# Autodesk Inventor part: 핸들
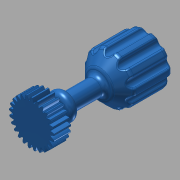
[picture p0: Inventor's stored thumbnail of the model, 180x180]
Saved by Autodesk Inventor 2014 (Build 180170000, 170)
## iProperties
Created: 2017-04
Part Number: 핸들
Material: 강철, 연강
Document SubType Name: Modeling
Designer: mduedu
Categories: <?xml version="1.0" encoding="UTF-16"?> <MemberInstance><Categories><FamilyTemplate><FamilyTemplateParameter ValueType="xs:double" Id="1" ObjectReferenceKey="da
Density: 7.86 g/cm^3
Appearance: 청록색
Mass: 193.539 g
Surface Area: 74.5308 cm^2
Volume: 24.6233 cm^3
CustomPartVersion: 1
Author: mduedu
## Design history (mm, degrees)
sketch "Sketch1"
  geometry: C1 r 13.5 at (0, 0)
  constraints: 1 centre point
  dimensions: "d0" = 27 diameter of C1 (= da_da)
extrude "Extrusion1" new body sketch "Sketch1" distance "d1" = 10 (= da_b); taper "d2" = 0 deg
workplane "Work Plane2"
sketch "Sketch2"
  geometry: C1 r 13.5 at (0, 0) reference; C2 r 12.5 at (0, 0)
  constraints: 1 centre point, 1 coincident
  dimensions: "d3" = 25 diameter of C2 (= da_dw)
feature "피치 지름" sketch "Sketch2" dims "d4" = 10, "d5" = 0
workplane "Work Plane8"
workplane "Work Plane9"
feature "스퍼 기어" dims "da_b" = 10, "da_d" = 25, "da_aw" = 25, "da_da" = 27, "da_df" = 22.5, "da_dw" = 25, angle "da_beta" = 0 deg, "da_lefttooth" = 0, "da_righttooth" = 0
sketch "스케치3"
  geometry: C1 r 5 at (0, 0); 1 further point
  constraints: 1 centre point, 1 coincident
  dimensions: "d49" = 10 diameter of C1
extrude "돌출2" join sketch "스케치3" distance "d50" = 60; taper "d51" = 0 deg
sketch "스케치4"
  geometry: C1 r 15 at (0, 0); 1 further point
  constraints: 1 centre point, 1 coincident
  dimensions: "d52" = 30 diameter of C1
extrude "돌출3" join sketch "스케치4" distance "d53" = 30; taper "d54" = 0 deg
chamfer "모따기1" distance "d55" = 7; stored, may be unused: second distance "d56" = 2, angle "d57" = 45 deg
sketch "스케치5"
  geometry: L1 (0, 2.2)-(0, -13.2) reference; L2 (0, -5)-(8, -5); L3 (8, -5)-(8, -11); L4 (8, -11)-(0, -11); L5 (0, -11)-(0, -5); 1 further point
  constraints: 8 end point, 2 parallel, 1 horizontal, 1 perpendicular, 1 point on line
  dimensions: "d58" = 5 distance from line of L2 point (0, 0); "d59" = 6 distance of L2.end L3.end; "d60" = 16 diameter of L3 L1
revolve "회전1" sketch "스케치5" stored, may be unused: angle "d61" = 90 deg
fillet "모깎기1" dims "d62" = 3
fillet "모깎기2" dims "d65" = 3
fillet "모깎기3" dims "d72" = 3
sketch "스케치6"
  geometry: C1 r 2.5 at (0, 15); 2 further points
  constraints: 2 vertical alignment, 1 centre point, 1 other
  dimensions: "d66" = 5 diameter of C1
extrude "돌출4" cut sketch "스케치6" stored distance "d67" = 35; taper "d68" = 0 deg
fillet "모깎기4" dims "d73" = 1
body "Solid1"
pattern_circular "원형 패턴2" dims angle "d75" = 360 deg
body "Srf1"
other parameters: "d16" = 25 (= da_aw), "d17" = 0, "d34" = 1.25664 (computed from da_z), "d39" = 0, "d41" = 0, "d43" = 25 (= da_aw), "d46" = 25 (= da_aw), "d47" = 0, "d48" = 0
